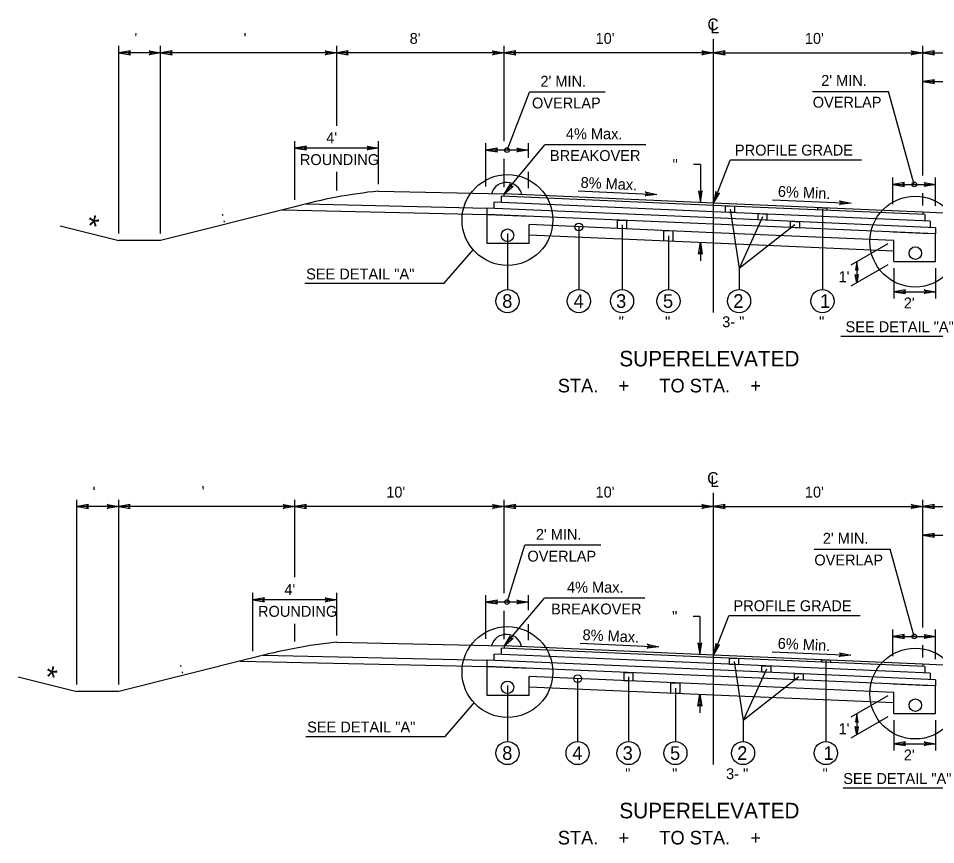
# Model space of a CAD drawing. Extents: x -540 to 1231, y -564 to 421.
# Drawn here: x 492.7 to 610.8, y 63.3 to 169.5 of the extents above; entities that cross this region are included whole.
import ezdxf

# ---------------------------------------------------------------- set-up
doc = ezdxf.new("R2010")
doc.units = 0
doc.layers.add('1', color=7, linetype='Continuous')
doc.layers.add('Des_ Drain_ Ftrs', color=7, linetype='Continuous')

msp = doc.modelspace()

# ---------------------------------------------------------------- linework, layer by layer
at = {"layer": '1'}
for p, q in [((582.17, 131.7), (582.17, 166.88)), ((505.63, 141.87), (505.63, 166)), ((511.02, 141.87), (511.02, 166)), ((533.68, 155.73), (533.68, 166)), ((555.23, 153.74), (555.23, 166)), ((609.12, 149.32), (609.12, 166)), ((511.02, 165.12), (505.63, 165.12)), ((533.68, 165.12), (511.02, 165.12)), ((555.23, 165.12), (533.68, 165.12)), ((582.17, 165.12), (555.23, 165.12)), ((582.17, 165.12), (609.12, 165.12)), ((609.12, 165.12), (630.67, 165.12)), ((609.12, 161.42), (636.87, 161.42)), ((555.6, 152.61), (558.47, 160.06)), ((568.24, 160.06), (558.47, 160.06)), ((594.91, 160.16), (604.68, 160.16)), ((608.01, 148.19), (604.68, 160.16)), ((528.29, 146.19), (528.29, 153.75)), ((539.07, 148.2), (539.07, 153.75)), ((552.86, 147.9), (552.86, 153.49)), ((558.34, 151.6), (558.34, 153.49)), ((539.07, 152.87), (528.29, 152.87)), ((558.34, 152.61), (552.86, 152.61)), ((555.23, 146.97), (560.48, 153.3)), ((573.45, 153.3), (560.48, 153.3)), ((555.23, 147.85), (555.23, 151.49)), ((582.18, 145.78), (584.31, 151.31)), ((601.23, 151.31), (584.31, 151.31)), ((580.48, 150.74), (579.6, 150.74)), ((580.48, 150.74), (580.48, 145.86)), ((533.68, 147.42), (533.68, 149.82)), ((558.34, 147.71), (558.34, 149.82)), ((605.27, 145.66), (605.27, 149.07)), ((610.76, 145.42), (610.76, 149.07)), ((605.27, 148.19), (610.76, 148.19)), ((539.07, 147.32), (555.23, 146.97)), ((582.17, 145.49), (554.89, 146.68)), ((554.89, 145.87), (554.89, 146.68)), ((582.17, 145.79), (555.23, 146.97)), ((555.23, 146.67), (555.23, 146.97)), ((564.76, 147.35), (574.87, 146.91)), ((609.12, 145.49), (609.12, 147.06)), ((528.29, 145.31), (511.02, 140.99)), ((529.7, 145.68), (553, 145.14)), ((582.17, 144.68), (553.96, 145.91)), ((553.96, 145.1), (553.96, 145.91)), ((609.12, 144.61), (582.17, 145.79)), ((609.35, 144.3), (582.17, 145.49)), ((589.76, 146.22), (599.87, 145.77)), ((526.7, 144.91), (553.04, 144.33)), ((582.17, 143.87), (553.04, 145.14)), ((553.04, 144.33), (553.04, 145.14)), ((553.04, 140.58), (553.04, 144.33)), ((582.17, 143.06), (553.04, 144.33)), ((553.04, 144.33), (555.23, 144.24)), ((555.23, 144.24), (558.53, 144.09)), ((610.06, 143.46), (582.17, 144.68)), ((584.3, 144.99), (585.46, 137.37)), ((596.19, 145), (596.19, 134.67)), ((625.28, 143.91), (609.12, 144.61)), ((609.12, 144.61), (609.12, 144.31)), ((609.35, 144.3), (609.35, 143.49)), ((498.09, 142.87), (505.63, 140.99)), ((582.17, 141.98), (558.43, 143.02)), ((558.43, 140.58), (558.43, 143.02)), ((570.4, 143.01), (570.4, 134.67)), ((610.76, 142.62), (582.17, 143.87)), ((610.76, 141.81), (582.17, 143.06)), ((588.48, 144.01), (585.46, 137.37)), ((592.65, 143), (585.46, 137.37)), ((610.06, 143.46), (610.06, 142.65)), ((555.66, 141.88), (555.66, 141.88)), ((555.66, 141.88), (555.66, 134.67)), ((582.17, 140.63), (558.43, 141.67)), ((564.84, 142.72), (564.84, 134.67)), ((605.37, 140.97), (582.17, 141.98)), ((609.12, 141.89), (605.28, 142.05)), ((610.76, 141.81), (609.12, 141.89)), ((610.76, 142.62), (610.76, 141.81)), ((610.76, 138.28), (610.76, 141.81)), ((511.02, 140.99), (505.63, 140.99)), ((558.43, 140.58), (553.04, 140.58)), ((576.37, 141.59), (576.37, 134.67)), ((580.48, 140.71), (580.48, 138.34)), ((605.37, 139.62), (582.17, 140.63)), ((604.61, 140.53), (599.85, 137.78)), ((605.37, 138.28), (605.37, 140.97)), ((605.37, 140.97), (605.37, 140.97)), ((547.5, 135.47), (551.24, 139.79)), ((600.62, 138.22), (600.6, 135.52)), ((605.37, 138.28), (610.76, 138.28)), ((585.46, 137.37), (585.46, 134.67)), ((604.61, 137.84), (599.84, 135.08)), ((605.37, 137.4), (605.37, 133.51)), ((610.76, 137.4), (610.76, 133.51)), ((529.57, 135.47), (547.5, 135.47)), ((605.37, 134.39), (610.76, 134.39)), ((598.58, 128.67), (617.37, 128.67)), ((500.24, 83.84), (500.24, 107.63)), ((505.63, 83.84), (505.63, 107.63)), ((528.29, 97.67), (528.29, 107.63)), ((555.23, 95.6), (555.23, 107.63)), ((582.17, 73.55), (582.17, 108.51)), ((609.12, 91.17), (609.12, 107.63)), ((505.63, 106.75), (500.24, 106.75)), ((528.29, 106.75), (505.63, 106.75)), ((555.23, 106.75), (528.29, 106.75)), ((582.17, 106.75), (555.23, 106.75)), ((582.17, 106.75), (609.12, 106.75)), ((609.12, 106.75), (636.06, 106.75)), ((609.12, 103.05), (642.48, 103.05)), ((555.6, 94.47), (557.88, 101.77)), ((567.65, 101.77), (557.88, 101.77)), ((595.12, 101.27), (604.89, 101.27)), ((608.01, 90.04), (604.89, 101.27)), ((522.9, 88.16), (522.9, 95.64)), ((533.68, 90.17), (533.68, 95.64)), ((533.68, 94.76), (522.9, 94.76)), ((552.86, 89.75), (552.86, 95.35)), ((558.34, 94.47), (552.86, 94.47)), ((555.23, 88.82), (560.41, 94.97)), ((558.34, 93.4), (558.34, 95.35)), ((573.34, 94.97), (560.41, 94.97)), ((555.23, 89.7), (555.23, 93.34)), ((580.42, 92.6), (579.54, 92.6)), ((580.42, 92.6), (580.42, 87.72)), ((582.18, 87.64), (584.14, 92.71)), ((601.06, 92.71), (584.14, 92.71)), ((528.29, 89.39), (528.29, 91.68)), ((558.34, 89.56), (558.34, 91.63)), ((605.27, 87.51), (605.27, 90.92)), ((610.76, 87.13), (610.76, 90.92)), ((605.27, 90.04), (610.76, 90.04)), ((533.68, 89.29), (555.23, 88.82)), ((582.17, 87.64), (555.23, 88.82)), ((555.23, 88.82), (555.23, 88.52)), ((565, 89.16), (575.12, 88.72)), ((609.12, 87.35), (609.12, 88.91)), ((524.23, 87.63), (553.04, 87)), ((582.17, 86.54), (553.96, 87.77)), ((553.96, 86.96), (553.96, 87.77)), ((582.17, 87.34), (554.89, 88.54)), ((554.89, 87.73), (554.89, 88.54)), ((609.12, 86.47), (582.17, 87.64)), ((589.74, 88.07), (599.85, 87.63)), ((522.9, 87.28), (505.63, 82.96)), ((521.31, 86.88), (553.04, 86.19)), ((582.17, 85.73), (553.04, 87)), ((553.04, 86.19), (553.04, 87)), ((553.04, 82.43), (553.04, 86.19)), ((582.17, 84.92), (553.04, 86.19)), ((553.04, 86.19), (555.23, 86.09)), ((609.35, 86.16), (582.17, 87.34)), ((610.06, 85.32), (582.17, 86.54)), ((584.81, 86.83), (585.97, 79.21)), ((596.63, 86.85), (596.63, 76.52)), ((630.67, 85.53), (609.12, 86.47)), ((609.12, 86.47), (609.12, 86.17)), ((555.23, 86.09), (558.53, 85.95)), ((610.76, 84.48), (582.17, 85.73)), ((588.98, 85.85), (585.97, 79.21)), ((609.35, 86.16), (609.35, 85.35)), ((610.06, 85.32), (610.06, 84.51)), ((492.7, 84.84), (500.24, 82.96)), ((582.17, 83.84), (558.43, 84.88)), ((558.43, 82.43), (558.43, 84.88)), ((564.68, 84.6), (564.68, 76.52)), ((571.24, 84.86), (571.24, 76.52)), ((610.76, 83.67), (582.17, 84.92)), ((605.37, 82.83), (582.17, 83.84)), ((593.16, 84.84), (585.97, 79.21)), ((609.12, 83.74), (605.28, 83.91)), ((610.76, 84.48), (610.76, 83.67)), ((505.63, 82.96), (500.24, 82.96)), ((555.66, 83.74), (555.66, 83.74)), ((555.66, 83.74), (555.66, 76.52)), ((582.17, 82.49), (558.43, 83.53)), ((577.27, 83.39), (577.27, 76.52)), ((605.37, 80.13), (605.37, 82.82)), ((605.37, 82.82), (605.37, 82.82)), ((610.76, 83.67), (609.12, 83.74)), ((610.76, 80.13), (610.76, 83.67)), ((547.62, 77.18), (551.36, 81.5)), ((558.43, 82.43), (553.04, 82.43)), ((580.42, 82.57), (580.42, 80.2)), ((605.37, 81.48), (582.17, 82.49)), ((604.61, 82.38), (599.85, 79.64)), ((585.97, 79.21), (585.97, 76.52)), ((604.61, 79.69), (599.84, 76.94)), ((600.62, 80.08), (600.6, 77.37)), ((605.37, 80.13), (610.76, 80.13)), ((605.37, 79.25), (605.37, 75.36)), ((610.76, 79.25), (610.76, 75.36)), ((529.69, 77.18), (547.62, 77.18)), ((605.37, 76.24), (610.76, 76.24)), ((598.86, 70.56), (617.65, 70.56))]:
    msp.add_line(p, q, dxfattribs=at)
for points in [[(583.73, 145.42), (584.87, 145.37), (584.87, 144.56), (583.73, 144.61)], [(587.9, 144.43), (589.05, 144.38), (589.05, 143.57), (587.9, 143.62)], [(595.61, 145.2), (596.76, 145.15), (596.76, 144.85), (595.61, 144.9)], [(569.82, 143.6), (570.97, 143.55), (570.97, 142.47), (569.82, 142.52)], [(592.08, 143.44), (593.22, 143.39), (593.22, 142.58), (592.08, 142.63)], [(575.79, 142.26), (576.94, 142.21), (576.94, 140.86), (575.79, 140.91)], [(584.23, 87.25), (585.38, 87.2), (585.38, 86.4), (584.23, 86.45)], [(588.41, 86.26), (589.56, 86.21), (589.56, 85.4), (588.41, 85.45)], [(596.06, 87.04), (597.21, 86.99), (597.21, 86.69), (596.06, 86.74)], [(570.66, 85.42), (571.81, 85.37), (571.81, 84.29), (570.66, 84.34)], [(593.73, 85.22), (593.73, 84.41), (592.58, 84.46), (592.58, 85.27)], [(576.7, 84.08), (577.85, 84.03), (577.85, 82.68), (576.7, 82.73)]]:
    msp.add_lwpolyline(points, close=True, dxfattribs=at)
for centre, radius in [((555.6, 152.61), 0.3), ((555.65, 143.61), 5.84), ((608.01, 148.19), 0.3), ((608.14, 140.83), 5.84), ((564.84, 142.72), 0.5), ((555.66, 141.65), 0.808), ((608.15, 139.35), 0.808), ((555.66, 133.18), 1.49), ((564.84, 133.18), 1.49), ((570.4, 133.18), 1.49), ((576.37, 133.18), 1.49), ((585.46, 133.18), 1.49), ((596.19, 133.18), 1.49), ((555.6, 94.47), 0.3), ((555.65, 85.46), 5.84), ((608.01, 90.04), 0.3), ((608.14, 82.69), 5.84), ((564.68, 84.6), 0.5), ((555.66, 83.5), 0.808), ((608.15, 81.2), 0.808), ((555.66, 75.04), 1.49), ((564.68, 75.04), 1.49), ((571.24, 75.04), 1.49), ((577.27, 75.04), 1.49), ((585.97, 75.04), 1.49), ((596.63, 75.04), 1.49)]:
    msp.add_circle(centre, radius, dxfattribs=at)
for centre, radius, start, end in [((555.54, 146.45), 2, 12.002, 163.2641), ((545.96, 80.49), 67.19, 95.8897, 105.2483), ((555.52, 88.31), 2, 12.0711, 163.8353), ((540.58, 22.46), 67.19, 95.8911, 105.2497)]:
    msp.add_arc(centre, radius, start, end, dxfattribs=at)
at = {"layer": 'Des_ Drain_ Ftrs'}
for points in [[(505.63, 165.12), (507.12, 164.87), (506.82, 165.12), (507.12, 165.37)], [(511.02, 165.12), (509.53, 164.87), (509.82, 165.12), (509.53, 165.37)], [(511.02, 165.12), (512.5, 164.87), (512.21, 165.12), (512.5, 165.37)], [(533.68, 165.12), (532.19, 164.87), (532.49, 165.12), (532.19, 165.37)], [(533.68, 165.12), (535.17, 164.87), (534.87, 165.12), (535.17, 165.37)], [(555.23, 165.12), (553.74, 164.87), (554.04, 165.12), (553.74, 165.37)], [(555.23, 165.12), (556.72, 164.87), (556.43, 165.12), (556.72, 165.37)], [(582.17, 165.12), (580.69, 164.87), (580.98, 165.12), (580.69, 165.37)], [(582.17, 165.12), (583.66, 164.87), (583.37, 165.12), (583.66, 165.37)], [(609.12, 165.12), (607.63, 164.87), (607.92, 165.12), (607.63, 165.37)], [(609.12, 165.12), (610.6, 164.87), (610.31, 165.12), (610.6, 165.37)], [(609.12, 161.42), (610.6, 161.17), (610.31, 161.42), (610.6, 161.66)], [(528.29, 152.87), (529.78, 152.62), (529.48, 152.87), (529.78, 153.12)], [(539.07, 152.87), (537.58, 152.62), (537.87, 152.87), (537.58, 153.12)], [(552.86, 152.61), (554.35, 152.37), (554.05, 152.61), (554.35, 152.86)], [(558.34, 152.61), (556.85, 152.37), (557.15, 152.61), (556.85, 152.86)], [(555.23, 146.97), (556.37, 147.95), (555.99, 147.88), (555.99, 148.27)], [(605.27, 148.19), (606.76, 147.94), (606.46, 148.19), (606.76, 148.44)], [(610.76, 148.19), (609.27, 147.94), (609.56, 148.19), (609.27, 148.44)], [(574.87, 146.91), (573.37, 146.72), (573.68, 146.96), (573.39, 147.22)], [(580.48, 145.86), (580.73, 147.35), (580.48, 147.06), (580.23, 147.35)], [(582.18, 145.78), (582.95, 147.08), (582.61, 146.9), (582.48, 147.26)], [(599.87, 145.77), (598.38, 145.59), (598.68, 145.83), (598.4, 146.09)], [(580.48, 140.71), (580.73, 139.22), (580.48, 139.52), (580.23, 139.22)], [(600.62, 138.22), (600.43, 137.14), (600.61, 137.35), (600.79, 137.14)], [(600.6, 135.52), (600.42, 136.6), (600.6, 136.39), (600.78, 136.6)], [(605.37, 134.39), (606.86, 134.14), (606.57, 134.39), (606.86, 134.64)], [(610.76, 134.39), (609.27, 134.14), (609.57, 134.39), (609.27, 134.64)], [(500.24, 106.75), (501.73, 106.51), (501.43, 106.75), (501.73, 107)], [(505.63, 106.75), (504.14, 106.51), (504.43, 106.75), (504.14, 107)], [(505.63, 106.75), (507.11, 106.51), (506.82, 106.75), (507.11, 107)], [(528.29, 106.75), (526.8, 106.51), (527.1, 106.75), (526.8, 107)], [(528.29, 106.75), (529.78, 106.51), (529.49, 106.75), (529.78, 107)], [(555.23, 106.75), (553.74, 106.51), (554.04, 106.75), (553.74, 107)], [(555.23, 106.75), (556.72, 106.51), (556.43, 106.75), (556.72, 107)], [(582.17, 106.75), (580.69, 106.51), (580.98, 106.75), (580.69, 107)], [(582.17, 106.75), (583.66, 106.51), (583.37, 106.75), (583.66, 107)], [(609.12, 106.75), (607.63, 106.51), (607.92, 106.75), (607.63, 107)], [(609.12, 106.75), (610.6, 106.51), (610.31, 106.75), (610.6, 107)], [(609.12, 103.05), (610.6, 102.8), (610.31, 103.05), (610.6, 103.3)], [(522.9, 94.76), (524.39, 94.51), (524.1, 94.76), (524.39, 95.01)], [(533.68, 94.76), (532.19, 94.51), (532.49, 94.76), (532.19, 95.01)], [(552.86, 94.47), (554.35, 94.22), (554.05, 94.47), (554.35, 94.72)], [(558.34, 94.47), (556.85, 94.22), (557.15, 94.47), (556.85, 94.72)], [(555.23, 88.82), (556.38, 89.8), (556, 89.73), (556, 90.12)], [(605.27, 90.04), (606.76, 89.79), (606.46, 90.04), (606.76, 90.29)], [(610.76, 90.04), (609.27, 89.79), (609.56, 90.04), (609.27, 90.29)], [(575.12, 88.72), (573.62, 88.54), (573.92, 88.77), (573.64, 89.03)], [(580.42, 87.72), (580.67, 89.21), (580.42, 88.91), (580.17, 89.21)], [(582.18, 87.64), (582.95, 88.94), (582.61, 88.75), (582.48, 89.12)], [(599.85, 87.63), (598.35, 87.45), (598.66, 87.69), (598.38, 87.95)], [(580.42, 82.57), (580.67, 81.08), (580.42, 81.38), (580.17, 81.08)], [(600.62, 80.08), (600.43, 79), (600.61, 79.21), (600.79, 78.99)], [(600.6, 77.37), (600.42, 78.46), (600.6, 78.24), (600.78, 78.46)], [(605.37, 76.24), (606.86, 76), (606.57, 76.24), (606.86, 76.49)], [(610.76, 76.24), (609.27, 76), (609.57, 76.24), (609.27, 76.49)]]:
    msp.add_lwpolyline(points, close=True, dxfattribs=at)

# ---------------------------------------------------------------- texts
at = {"layer": '1'}
for s, height, p in [(" '", 1.4, (507.13, 166.27)), ("  '", 1.4, (520.65, 166.27)), ("8'", 1.4, (543.07, 166.27)), ("10'", 1.4, (566.99, 166.27)), ("10'", 1.4, (593.93, 166.27)), ("2' MIN.", 1.4, (559.9, 160.76)), ("2' MIN.", 1.4, (596.03, 160.86)), ('OVERLAP', 1.4, (558.81, 157.96)), ('OVERLAP', 1.4, (594.94, 158.06)), ("4'", 1.4, (532.33, 153.48)), ('4% Max.', 1.4, (563.17, 154)), ('BREAKOVER', 1.4, (561.12, 151.2)), ('PROFILE GRADE', 1.4, (584.93, 151.9)), ('ROUNDING', 1.4, (528.94, 150.68)), ('SEE DETAIL "A"', 1.4, (529.75, 135.97)), ('8', 1.75, (554.98, 132.31)), ('4', 1.75, (564.17, 132.31)), ('3', 1.75, (569.64, 132.31)), ('5', 1.75, (575.67, 132.31)), ('2', 1.75, (584.72, 132.31)), ('1', 1.75, (595.88, 132.31)), ("2'", 1.4, (606.66, 132.24)), (' "', 1.4, (569.45, 129.82)), (' "', 1.4, (575.42, 129.82)), ('3- "', 1.4, (583.29, 129.82)), (' "', 1.4, (595.24, 129.82)), ('SEE DETAIL "A"', 1.4, (599.17, 129.18)), ('SUPERELEVATED', 2, (570.05, 124.78)), ('STA.    +      TO STA.    +     ', 1.75, (562.14, 121.43)), (" '", 1.4, (501.74, 107.91)), ("  '", 1.4, (515.26, 107.98)), ("10'", 1.4, (540.05, 107.91)), ("10'", 1.4, (566.99, 107.91)), ("10'", 1.4, (593.93, 107.91)), ("2' MIN.", 1.4, (559.31, 102.47)), ("2' MIN.", 1.4, (596.24, 101.97)), ('OVERLAP', 1.4, (558.22, 99.67)), ('OVERLAP', 1.4, (595.15, 99.17)), ('4% Max.', 1.4, (563.31, 95.67)), ("4'", 1.4, (526.94, 95.37)), ('PROFILE GRADE', 1.4, (584.75, 93.29)), ('ROUNDING', 1.4, (523.55, 92.57)), ('BREAKOVER', 1.4, (561.26, 92.87)), ('SEE DETAIL "A"', 1.4, (529.88, 77.69)), ('8', 1.75, (554.98, 74.16)), ('4', 1.75, (564, 74.16)), ('3', 1.75, (570.48, 74.16)), ('5', 1.75, (576.58, 74.16)), ('2', 1.75, (585.22, 74.16)), ('1', 1.75, (596.33, 74.16)), ("2'", 1.4, (606.66, 74.09)), (' "', 1.4, (570.29, 71.68)), (' "', 1.4, (576.33, 71.68)), ('3- "', 1.4, (583.79, 71.68)), (' "', 1.4, (595.69, 71.68)), ('SEE DETAIL "A"', 1.4, (598.87, 71.06)), ('SUPERELEVATED', 2, (570.05, 66.64)), ('STA.    +      TO STA.    +     ', 1.75, (562.14, 63.28))]:
    msp.add_text(s, height=height, dxfattribs=at).set_placement(p)
for s, height, rotation, p in [('  "', 1.4, 0.1438, (575.87, 150.04)), ('8% Max.', 1.4, 357.3761, (565.04, 147.76)), ('6% Min.', 1.4, 357.3731, (590.43, 146.61)), ('*', 2.8, 347.1521, (501.26, 141.63)), (' : ', 1.4, 14.2282, (518.47, 143.13)), ("1'", 1.4, 0.1438, (598.27, 135.61)), ('  "', 1.4, 0.1438, (575.81, 91.9)), ('8% Max.', 1.4, 357.3762, (565.29, 89.58)), ('6% Min.', 1.4, 357.3732, (590.41, 88.47)), ('*', 2.8, 347.1521, (495.87, 83.61)), (' : ', 1.4, 14.2282, (513.09, 85.11)), ("1'", 1.4, 0.1438, (598.27, 77.46))]:
    msp.add_text(s, height=height, rotation=rotation, dxfattribs=at).set_placement(p)
at = {"layer": 'Des_ Drain_ Ftrs'}
for s, p in [('C', (581.39, 168.03)), ('L', (581.79, 167.63)), ('C', (581.36, 109.67)), ('L', (581.75, 109.27))]:
    msp.add_text(s, height=1.5, dxfattribs=at).set_placement(p)

doc.saveas('drawing.dxf')
